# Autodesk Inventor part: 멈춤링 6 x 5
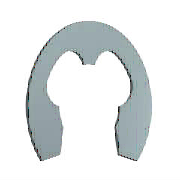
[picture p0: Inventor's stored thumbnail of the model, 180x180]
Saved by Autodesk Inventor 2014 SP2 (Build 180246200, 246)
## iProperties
Created: 2012-02
Part Number: 멈춤링 6 x 5
Material: 강철, 연강
Description: 스프링 리테이닝 링
Document SubType Name: Modeling
Standard: JIS B 2805
Designer: mduedu
Standards Organization: JIS
Language: ko-KR
Size Designation: 5
Categories: <MemberInstance><Categories><Category DisplayName="샤프트 부품" InternalName="7f7aeb1f-a693-4053-b835-cee3144e0d98" Mnemonic="SHFT"><Category DisplayName="써클립" Inter
Density: 1 g/cm^3
Appearance: 파란색 - 벽 페인트 - 광택
IsCustomPart: 1
Author: mduedu
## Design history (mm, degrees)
sketch "스케치1"
  geometry: L1 (-0.5, 0.024)-(0, 0.024) reference; L2 (-3.206, 0)-(3.486, 0) reference; L3 (-2.291, -3.976)-(2.291, -3.976); L4 (0, 1.949)-(0, -3.479) reference; L5 (-3, -1.976)-(-2.51, -1.976); L6 (-0.5, 0.024)-(-0.5, 0.509); L7 (0, 2.524)-(2.53, 2.524); L8 (-2.291, -3.976)-(-3.051, -6.131); L9 (0, -0.476)-(-1.278, -0.476); L10 (2.291, -3.976)-(3.051, -6.131); L11 (3, -1.976)-(2.51, -1.976); L12 (0.5, 0.024)-(0.5, 0.509); C1 r 3 at (0, -2.976); A1 r 2.5 centre (0, -2.976) between (-2.368, -2.174) and (-2.291, -3.976); A2 r 0.5 centre (0, 0.024) between (-0.5, 0.024) and (0.5, 0.024); A3 r 5.5 centre (0, -2.976) between (4.351, -6.34) and (-4.351, -6.34); A4 r 4 centre (0, -2.976) between (-1, 0.897) and (-3.529, -1.094); A5 r 0.4 centre (-0.9, 0.509) between (-0.5, 0.509) and (-1, 0.897); A6 r 0.6 centre (-3, -1.376) between (-3.529, -1.094) and (-3, -1.976); A7 r 0.15 centre (-2.51, -2.126) between (-2.368, -2.174) and (-2.51, -1.976); A8 r 0.75 centre (-3.758, -5.881) between (-4.351, -6.34) and (-3.051, -6.131); A9 r 0.75 centre (3.758, -5.881) between (3.051, -6.131) and (4.351, -6.34); A10 r 2.5 centre (0, -2.976) between (2.291, -3.976) and (2.368, -2.174); A11 r 0.15 centre (2.51, -2.126) between (2.51, -1.976) and (2.368, -2.174); A12 r 0.6 centre (3, -1.376) between (3, -1.976) and (3.529, -1.094); A13 r 4 centre (0, -2.976) between (3.529, -1.094) and (1, 0.897); A14 r 0.4 centre (0.9, 0.509) between (1, 0.897) and (0.5, 0.509); 1 further point
  constraints: 30 point on circle, 20 end point, 15 centre point, 13 symmetric about line, 12 tangent, 8 point on line, 4 parallel, 2 coincident, 2 horizontal, 1 concentric, 1 perpendicular, 1 vertical alignment, 9 other
  dimensions: "d0" = 6 diameter of C1 (= WD); "d3" = 1 distance from line of A1.centre L3 (= 0.2 x ND); "d4" = 0.5 radius of A2 (= 0.1 x ND); "d5" = 11 diameter of A3 (= SD2); "d8" = 4 radius of A4 (= 0.8 x ND); "d9" = 1 distance from line of A1.centre L5 (= 0.2 x ND); "d10" = 0.4 radius of A5 (= 0.08 x ND); "d11" = 0.6 radius of A6 (= 0.12 x ND); "d12" = 0.15 radius of A7 (= 0.03 x ND); "d13" = 0.75 radius of A8 (= 0.15 x ND); "d14" = 2.5 distance from line of A1.centre L9 (= 0.5 x ND); "d15" = 2.5 radius of A1 (= 0.5 x ND)
extrude "본체" new body sketch "스케치1" distance "d16" = 0.6 (= SD); taper "d17" = 0 deg
workaxis "Work Axis1"
workaxis "Work Axis2"
workplane "Work Plane1"
body "Solid1"
other parameters: "ND" = 5 [user parameter; used in 14 equation terms], "SD" = 0.6 [user parameter; used in 1 equation term], "WD" = 6 (= WDMIN) [user parameter; used in 1 equation term], "d1" = 8 (= 1.6 x ND), "d2" = 5 (= ND), "SD2" = 11 [user parameter; used in 1 equation term], "d6" = 5 (= ND), "d7" = 0.75 (= 0.15 x ND), "d18" = 0, "d19" = 0, "d27" = 0, "d28" = 0, "WDMIN" = 6 [user parameter; used in 1 equation term], "SNB" = 0.7 [user parameter], "WDMAX" = 8 [user parameter], "BUBRMI" = 1.2 [user parameter]
